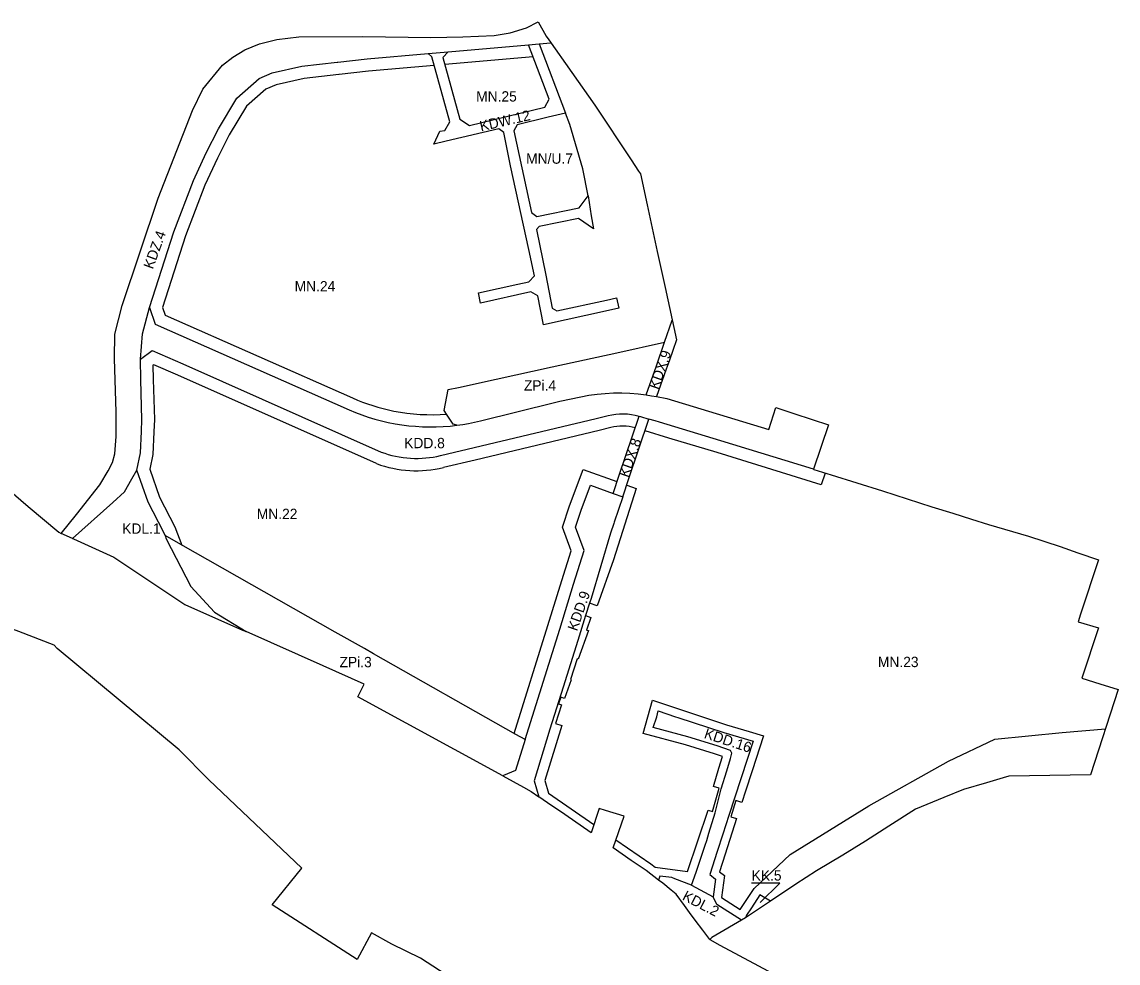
# Model space of a CAD drawing. Extents: x 7416797 to 7419013, y 5549660 to 5551534.
# Drawn here: x 7417878 to 7418410, y 5550444 to 5550900 of the extents above; entities that cross this region are included whole.
import ezdxf

# ---------------------------------------------------------------- set-up
doc = ezdxf.new("R2010")
doc.units = 0
for name, color, linetype in [('LIN_Linia Zabudowy Nieprzekraczalna', 7, 'Continuous'), ('LIN_linie_rozgraniczajace', 7, 'Continuous'), ('TXT_Oznaczenia_przeznaczen', 7, 'Continuous')]:
    doc.layers.add(name, color=color, linetype=linetype)

msp = doc.modelspace()

# ---------------------------------------------------------------- linework, layer by layer
at = {"layer": 'LIN_Linia Zabudowy Nieprzekraczalna'}
for p, q in [((7418126.06, 5550882.92), (7418083.23, 5550879.15)), ((7418078.16, 5550878.71), (7418046.26, 5550875.9)), ((7418157.99, 5550701.9), (7418097.98, 5550687.46)), ((7418163.75, 5550703.29), (7418157.99, 5550701.9)), ((7418191.8, 5550698.19), (7418180.27, 5550701.72)), ((7418097.98, 5550687.46), (7418082.58, 5550683.86)), ((7418267.61, 5550681.23), (7418265.7, 5550675.57))]:
    msp.add_line(p, q, dxfattribs=at)
for points in [[(7418031.82, 5550874.32), (7418015.02, 5550872.49), (7418001.5, 5550869.36), (7417996.53, 5550867.28), (7417987.21, 5550859), (7417978.79, 5550845.04), (7417973.03, 5550833.84), (7417966.95, 5550820.66), (7417957.58, 5550796.15), (7417946.42, 5550761.49)], [(7418046.26, 5550875.9), (7418032.1, 5550874.36), (7418031.82, 5550874.32)], [(7417946.42, 5550761.49), (7417947.75, 5550757.79), (7418038.53, 5550717.6)], [(7417941.78, 5550733.43), (7417941.91, 5550726.51), (7417942.51, 5550707.1), (7417942.32, 5550701.15), (7417941.8, 5550690.16), (7417940.27, 5550683.06)], [(7418050.17, 5550685.8), (7417953.84, 5550728.69), (7417942.18, 5550733.72), (7417941.78, 5550733.43)], [(7418265.7, 5550675.57), (7418215.23, 5550691.15), (7418191.8, 5550698.19)], [(7417940.27, 5550683.06), (7417945.01, 5550669.57), (7417952.44, 5550655.21), (7417955.9, 5550646.22)], [(7418116.82, 5550555.06), (7418133.18, 5550607.33), (7418139.94, 5550629.08), (7418144.45, 5550643.49), (7418140.22, 5550654.98), (7418143.68, 5550665.31), (7418150.29, 5550682.95), (7418166.68, 5550677.05)], [(7418171.38, 5550675.35), (7418176.02, 5550673.68)], [(7418176.02, 5550673.68), (7418164.94, 5550639.2), (7418157.08, 5550616.94), (7418153.41, 5550618.18), (7418151.42, 5550612.12), (7418153.97, 5550611.25), (7418151.97, 5550605.14), (7418152.82, 5550604.85), (7418147.94, 5550591.03), (7418147.45, 5550591.19), (7418144.08, 5550581.18), (7418144.43, 5550581.07), (7418141.29, 5550572.05), (7418139.41, 5550572.67), (7418138.33, 5550569.4), (7418139.78, 5550568.92), (7418136.87, 5550559.86), (7418140.03, 5550558.85), (7418131.78, 5550532.23), (7418133.53, 5550526.03), (7418155.53, 5550510.86)], [(7418166.2, 5550503.51), (7418183.06, 5550491.9), (7418185.21, 5550490.27), (7418200.89, 5550488.22), (7418210.81, 5550517.86), (7418212.96, 5550517.24), (7418216.21, 5550528.54), (7418213.39, 5550529.33), (7418216.04, 5550538.15), (7418217.85, 5550543.87), (7418213.95, 5550545.2), (7418199.96, 5550549.57), (7418179.43, 5550555), (7418183.91, 5550571.09), (7418197.47, 5550566.61), (7418219.68, 5550559.27), (7418230.74, 5550556.04), (7418230.78, 5550556.03)], [(7418230.78, 5550556.03), (7418237.7, 5550553.9), (7418232.17, 5550536.92), (7418228.95, 5550527.03), (7418227.19, 5550521.63), (7418224.21, 5550522.51), (7418221.88, 5550514.66), (7418224.65, 5550513.84), (7418219.09, 5550496.54), (7418216.36, 5550488.05), (7418218.71, 5550486.13), (7418217.32, 5550475.49), (7418226.44, 5550469.7), (7418233.14, 5550479.88), (7418250.59, 5550496.35), (7418288.74, 5550520.04), (7418327.36, 5550541.65), (7418349.84, 5550552.32), (7418382.49, 5550555.45), (7418403.35, 5550557.34)]]:
    msp.add_lwpolyline(points, dxfattribs=at)
for centre, radius, start, end in [((7418076.72, 5550803.5), 94, 246.0302, 258.8512), ((7418076.72, 5550803.5), 94, 258.8512, 274.5258), ((7418169.36, 5550679.95), 24, 75.2383, 103.5317), ((7418069.58, 5550738.33), 56, 249.7218, 283.4289)]:
    msp.add_arc(centre, radius, start, end, dxfattribs=at)
at = {"layer": 'LIN_linie_rozgraniczajace'}
msp.add_line((7418202.86, 5550481.52), (7418213.35, 5550475.94), dxfattribs=at)
for points in [[(7417871.75, 5550673.2), (7417881.4, 5550665.03), (7417896.21, 5550652.5), (7417897.42, 5550651.95), (7417904.79, 5550661.06), (7417916.14, 5550675.54), (7417920.09, 5550682.27), (7417922.15, 5550686.34), (7417923.29, 5550690.46), (7417923.96, 5550698.93), (7417923.96, 5550710.7), (7417923.21, 5550736.79), (7417923.29, 5550748.57), (7417926.92, 5550762.35), (7417944.32, 5550814.46), (7417961.05, 5550856.89), (7417966.04, 5550867.27), (7417975.5, 5550878.9), (7417980.57, 5550882.81), (7417986.33, 5550886.37), (7417993.39, 5550889.27), (7418001.86, 5550891.33), (7418012.49, 5550892.66), (7418043.54, 5550892.72), (7418076.48, 5550892.36), (7418092.04, 5550892.67), (7418107.25, 5550893.28), (7418114.99, 5550894.55), (7418122.9, 5550896.9), (7418128.44, 5550899.83), (7418132.4, 5550892.89), (7418133.59, 5550891.2), (7418155.92, 5550859.51), (7418173.54, 5550832.99), (7418177.18, 5550827.51), (7418178.01, 5550826.26), (7418181.29, 5550811.16), (7418186.18, 5550788.63), (7418189.97, 5550771.19), (7418195.47, 5550745.84), (7418191.91, 5550735.48), (7418190.58, 5550731.6), (7418185.88, 5550718.24), (7418190.89, 5550717.39), (7418240.31, 5550702.29), (7418243.71, 5550712.91), (7418252.4, 5550710.11), (7418261.23, 5550707.12), (7418269.14, 5550704.53), (7418261.88, 5550683.03), (7418262.14, 5550682.95), (7418270.42, 5550680.35), (7418295.31, 5550672.54), (7418319.26, 5550664.87), (7418329.44, 5550661.72), (7418338.42, 5550658.94), (7418346.77, 5550656.35), (7418366.08, 5550650.65), (7418381.48, 5550645.57), (7418390.06, 5550642.57), (7418400, 5550639.09), (7418391.35, 5550612.87), (7418390.19, 5550609.18), (7418400.01, 5550606.16), (7418391.97, 5550581.75), (7418400.59, 5550579.06), (7418409.5, 5550576.28), (7418396.1, 5550535.06), (7418386.25, 5550534.87), (7418376.46, 5550534.68), (7418366.66, 5550534.5), (7418356.61, 5550534.3), (7418353.85, 5550533.49), (7418345.69, 5550531.09), (7418334.66, 5550527.85), (7418325.09, 5550523.95), (7418311.32, 5550518.33), (7418298.47, 5550510.1), (7418287.05, 5550502.8), (7418276.11, 5550496.1), (7418263.3, 5550488.48), (7418253.33, 5550481.97), (7418241.08, 5550473.75), (7418229.01, 5550465.67), (7418212.67, 5550456.1), (7418211.61, 5550455.11), (7418216.45, 5550452.52), (7418293.85, 5550411.16)], [(7418129.02, 5550889.21), (7418141.74, 5550855.68), (7418133.4, 5550853.68), (7418118.26, 5550850.04), (7418116.78, 5550847.1), (7418125.23, 5550807.54), (7418127.83, 5550805.62), (7418148.42, 5550809.67), (7418152.72, 5550815.53), (7418154.25, 5550805.85), (7418155.27, 5550799.56), (7418148.11, 5550804.58), (7418128.92, 5550800.75), (7418127.75, 5550799.26), (7418132.16, 5550777.07), (7418135.32, 5550761.16), (7418137.48, 5550759.84), (7418161.68, 5550765.02), (7418166.51, 5550766.08), (7418167.61, 5550761.09), (7418162.52, 5550759.97), (7418131.1, 5550753.07), (7418128.26, 5550767.07), (7418124.94, 5550768.99), (7418100.54, 5550763.62), (7418099.5, 5550768.58), (7418118.62, 5550772.78), (7418123.97, 5550773.95), (7418126.74, 5550776.83), (7418123.96, 5550789.58), (7418115.15, 5550830.04), (7418111.82, 5550846.29), (7418109.44, 5550848.04), (7418083.99, 5550842.03), (7418078.01, 5550840.65), (7418080.91, 5550846.82), (7418083.23, 5550847.27), (7418085.76, 5550851.46), (7418077, 5550882.86), (7418075.21, 5550884.47)], [(7418084.92, 5550885.32), (7418082.25, 5550882.67), (7418090.59, 5550852.78), (7418095.22, 5550849.58), (7418131.75, 5550858.51), (7418133.84, 5550862.33), (7418123.86, 5550888.75)], [(7418084.92, 5550885.32), (7418123.86, 5550888.75)], [(7418123.86, 5550888.75), (7418129.02, 5550889.21)], [(7418129.02, 5550889.21), (7418134.65, 5550889.7)], [(7417940.08, 5550761.38), (7417951.92, 5550798.15), (7417961.42, 5550822.99), (7417967.63, 5550836.47), (7417973.54, 5550847.96), (7417982.55, 5550862.88), (7417993.29, 5550872.43), (7417999.65, 5550875.09), (7418014.01, 5550878.42), (7418031.17, 5550880.29), (7418031.45, 5550880.32), (7418045.67, 5550881.87), (7418075.21, 5550884.47)], [(7418075.21, 5550884.47), (7418084.92, 5550885.32)], [(7418152.72, 5550815.53), (7418150.19, 5550828.67), (7418143.87, 5550850.07), (7418141.74, 5550855.68)], [(7417935.73, 5550736.44), (7417936.81, 5550748.73), (7417940.08, 5550761.38)], [(7417940.08, 5550761.38), (7417942.97, 5550753.34), (7418036.85, 5550711.82)], [(7418189.75, 5550744.59), (7418193.42, 5550755.27)], [(7418089.05, 5550704.37), (7418087.31, 5550704.83), (7418084.13, 5550709.79), (7418083.02, 5550711.53), (7418084.92, 5550721.66), (7418089.81, 5550722.73), (7418108.06, 5550726.72), (7418135.24, 5550732.66), (7418166.65, 5550739.54), (7418189.75, 5550744.59)], [(7418180.89, 5550719.13), (7418185.86, 5550733.24), (7418189.75, 5550744.59)], [(7417935.73, 5550736.44), (7417941.4, 5550740.59), (7417956.25, 5550734.18), (7418052.42, 5550691.36)], [(7417934.05, 5550682.66), (7417935.83, 5550690.94), (7417936.32, 5550701.38), (7417936.5, 5550707.1), (7417935.91, 5550726.36), (7417935.73, 5550736.44)], [(7418100.49, 5550706.49), (7418136.4, 5550715.45), (7418138.93, 5550715.99), (7418149.19, 5550718.17)], [(7418149.19, 5550718.17), (7418153.09, 5550718.91), (7418157.03, 5550719.47), (7418161.01, 5550719.85), (7418165, 5550720.06), (7418168.99, 5550720.09), (7418172.98, 5550719.95), (7418176.95, 5550719.62), (7418180.89, 5550719.13)], [(7418180.89, 5550719.13), (7418183.39, 5550718.72), (7418185.88, 5550718.24)], [(7418036.85, 5550711.82), (7418039.91, 5550710.55), (7418043.01, 5550709.39), (7418046.16, 5550708.33), (7418049.36, 5550707.36), (7418052.59, 5550706.51), (7418055.85, 5550705.76), (7418059.14, 5550705.12), (7418062.45, 5550704.59), (7418065.78, 5550704.17), (7418069.12, 5550703.87), (7418072.46, 5550703.67), (7418075.81, 5550703.59), (7418079.14, 5550703.62), (7418082.47, 5550703.76), (7418085.77, 5550704.01), (7418089.05, 5550704.37)], [(7418081.2, 5550689.7), (7418156.58, 5550707.73), (7418162.35, 5550709.12)], [(7418089.05, 5550704.37), (7418091.93, 5550704.77), (7418094.8, 5550705.26), (7418097.65, 5550705.83), (7418100.49, 5550706.49)], [(7418162.35, 5550709.12), (7418164.19, 5550709.51), (7418166.08, 5550709.77), (7418167.98, 5550709.92), (7418169.89, 5550709.95), (7418171.8, 5550709.86), (7418173.7, 5550709.64), (7418175.57, 5550709.31), (7418177.4, 5550708.86)], [(7418164.78, 5550671.35), (7418167.71, 5550680.13), (7418177.4, 5550708.86)], [(7418169.48, 5550669.66), (7418172.45, 5550678.54), (7418182.19, 5550707.4)], [(7418177.4, 5550708.86), (7418178.14, 5550708.64), (7418182.19, 5550707.4)], [(7418261.88, 5550683.03), (7418216.98, 5550696.89), (7418187.29, 5550705.81), (7418185.18, 5550706.49), (7418182.19, 5550707.4)], [(7418052.42, 5550691.36), (7418054.13, 5550690.78), (7418055.87, 5550690.25), (7418057.63, 5550689.78), (7418059.41, 5550689.37), (7418061.21, 5550689.03), (7418063.03, 5550688.76), (7418064.85, 5550688.55), (7418066.69, 5550688.41), (7418068.53, 5550688.34), (7418070.37, 5550688.34), (7418072.2, 5550688.4), (7418074.03, 5550688.53), (7418075.85, 5550688.73), (7418077.65, 5550688.99), (7418079.44, 5550689.31), (7418081.2, 5550689.7)], [(7417902.89, 5550649.49), (7417922.38, 5550666.92), (7417927.97, 5550672.18), (7417931.55, 5550678.4), (7417934.05, 5550682.66)], [(7417947.68, 5550650.88), (7417946.96, 5550652.75), (7417939.49, 5550667.19), (7417934.05, 5550682.66)], [(7418122.16, 5550552.04), (7418138.91, 5550605.54), (7418145.67, 5550627.3), (7418150.78, 5550643.65), (7418146.58, 5550655.07), (7418149.34, 5550663.3), (7418153.83, 5550675.3), (7418164.78, 5550671.35)], [(7418169.48, 5550669.66), (7418165.38, 5550657.38), (7418165.17, 5550656.79), (7418163.59, 5550652.04), (7418154.16, 5550620.38), (7418153.41, 5550618.18), (7418151.42, 5550612.12), (7418147.78, 5550600), (7418140.6, 5550577.39), (7418134.11, 5550557.17), (7418126.62, 5550532.12), (7418128.81, 5550524.35)], [(7418164.78, 5550671.35), (7418169.48, 5550669.66)], [(7417902.89, 5550649.49), (7417897.42, 5550651.95)], [(7417902.89, 5550649.49), (7417903.31, 5550649.3), (7417917.54, 5550642.89), (7417922.94, 5550640.46), (7417957.32, 5550617.55), (7417985.29, 5550605.13), (7417987.01, 5550604.37)], [(7417947.68, 5550650.88), (7417948.26, 5550649.37), (7417960.13, 5550626.23), (7417971.68, 5550613.78), (7417987.01, 5550604.37)], [(7418122.16, 5550552.04), (7418117.71, 5550554.55), (7418048.76, 5550593.62), (7418044.32, 5550596.13), (7418030.15, 5550604.16), (7417955.33, 5550646.54), (7417947.68, 5550650.88)], [(7418092.7, 5550432.42), (7418071.51, 5550446.22), (7418057.57, 5550452.93), (7418047.73, 5550458.5), (7418040.72, 5550445.49), (7417999.52, 5550471.94), (7418014.05, 5550489.79), (7417968.97, 5550532.54), (7417954.56, 5550547.11), (7417895.48, 5550596.2), (7417893.88, 5550597.78), (7417876.89, 5550604.46), (7417876.86, 5550604.47), (7417873.74, 5550605.53)], [(7418111.29, 5550534.45), (7418041.11, 5550572.74), (7418044.23, 5550578.96), (7418024.24, 5550587.84), (7417987.01, 5550604.37)], [(7418202.86, 5550481.52), (7418204.99, 5550487.89), (7418207.61, 5550495.61), (7418209.46, 5550500.87), (7418210.24, 5550503.14), (7418211.27, 5550506.64), (7418214.19, 5550516.61), (7418217.2, 5550528.14), (7418219.86, 5550536.97), (7418221.73, 5550542.89), (7418222.33, 5550545.48), (7418221.7, 5550546.79), (7418215.19, 5550549), (7418201.06, 5550553.41), (7418184.22, 5550557.87), (7418185.93, 5550563.05), (7418186.64, 5550565.98), (7418195.11, 5550563.17), (7418196.22, 5550562.82), (7418218.49, 5550555.45), (7418232.64, 5550551.27), (7418220.91, 5550515.28), (7418217.99, 5550506.19), (7418215.28, 5550497.76), (7418211.72, 5550486.68), (7418214.46, 5550484.44), (7418213.35, 5550475.94)], [(7418122.16, 5550552.04), (7418117.49, 5550537.08), (7418111.64, 5550534.6), (7418111.29, 5550534.45)], [(7418111.29, 5550534.45), (7418121.33, 5550528.97), (7418125.07, 5550526.95), (7418128.81, 5550524.35)], [(7418186.82, 5550484.02), (7418180.79, 5550488.6), (7418173.62, 5550493.54), (7418164.85, 5550499.58), (7418170.14, 5550515), (7418161.16, 5550517.77), (7418158.11, 5550518.71), (7418154.22, 5550506.89), (7418141.37, 5550515.74), (7418133.01, 5550521.42), (7418128.81, 5550524.35)], [(7418202.86, 5550481.52), (7418194.66, 5550484.64), (7418193.2, 5550485.19), (7418187.38, 5550485.95), (7418186.82, 5550484.02)], [(7418211.61, 5550455.11), (7418208.22, 5550459.67), (7418204.62, 5550464.58), (7418201.87, 5550468.27), (7418199.43, 5550471.68), (7418195.3, 5550477.11), (7418193.02, 5550479.12), (7418188.88, 5550482.45), (7418186.82, 5550484.02)], [(7418227.09, 5550464.55), (7418215.04, 5550472.2), (7418213.35, 5550475.94)], [(7418241.08, 5550473.75), (7418235.88, 5550476.76), (7418231.82, 5550470.59), (7418229.41, 5550466.93), (7418229.01, 5550465.67)], [(7418241.08, 5550473.75), (7418229.52, 5550466.01), (7418229.01, 5550465.67)]]:
    msp.add_lwpolyline(points, dxfattribs=at)
at = {"layer": 'TXT_Oznaczenia_przeznaczen'}
msp.add_lwpolyline([(7418236.07, 5550473.1), (7418245.59, 5550482.5), (7418231.93, 5550482.5)], dxfattribs=at)

# ---------------------------------------------------------------- texts
for s, p in [('MN.25', (7418098.44, 5550861.24)), ('MN/U.7', (7418122.67, 5550831.11)), ('MN.24', (7418010.48, 5550769.23)), ('ZPi.4', (7418121.58, 5550721.17)), ('KDD.8', (7418063.57, 5550693.26)), ('MN.22', (7417992.14, 5550658.91)), ('KDL.1', (7417926.93, 5550651.81)), ('ZPi.3', (7418032.24, 5550587.13)), ('MN.23', (7418293.12, 5550587.18)), ('KK.5', (7418231.93, 5550483.75))]:
    msp.add_text(s, height=5, dxfattribs=at).set_placement(p)
for s, rotation, p in [('KDW.12', 12.9972, (7418100.8, 5550846.74)), ('KDZ.4', 69.9762, (7417941.76, 5550779.7)), ('KDX.9', 70.7816, (7418186.74, 5550721.36)), ('KDX.8', 70.7816, (7418172.21, 5550678.72)), ('KDD.9', 70.7816, (7418147.3, 5550604.33)), ('KDD.16', 341.8712, (7418208.56, 5550552.92)), ('KDL.2', 332.5317, (7418197.98, 5550474.67))]:
    msp.add_text(s, height=5, rotation=rotation, dxfattribs=at).set_placement(p)

doc.saveas('drawing.dxf')
